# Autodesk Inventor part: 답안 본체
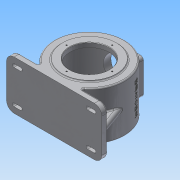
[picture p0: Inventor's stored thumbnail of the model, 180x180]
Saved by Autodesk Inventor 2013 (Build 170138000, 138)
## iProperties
Created: 2015-06
Part Number: 답안 본체
Material: 알루미늄 6061
Document SubType Name: Modeling
Designer: Administrator
Density: 2.71 g/cm^3
Mass: 3270.96 g
Surface Area: 2314.15 cm^2
Volume: 1207 cm^3
Author: Administrator
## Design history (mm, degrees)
sketch "스케치1"
  geometry: L1 (115, 14)-(115, 0); L2 (115, 0)-(-115, 0); L3 (-115, 0)-(-115, 14); L4 (-115, 14)-(-46.733, 14); L5 (46.733, 14)-(115, 14); A1 r 85 centre (0, 85) between (46.733, 14) and (-46.733, 14); 2 further points
  constraints: 10 end point, 3 parallel, 2 coincident, 2 horizontal, 2 perpendicular, 2 point on circle, 1 centre point, 1 collinear, 1 midpoint, 1 vertical alignment
  dimensions: "d1" = 85 distance of point (0, 0) A1.centre; "d2" = 230 distance between parallel lines of L1 L3; "d4" = 85 radius of A1; "d5" = 14 distance between parallel lines of L2 L5
extrude "돌출1" new body sketch "스케치1" distance "d6" = 118; taper "d7" = 0 deg
fillet "모깎기1" dims "d8" = 3
fillet "모깎기2" dims "d9" = 18
sketch "스케치2"
  geometry: L1 (-97, 0)-(97, 0) reference; C1 r 65 at (0, 85); A1 r 85 centre (0, 85) between (53.953, 19.318) and (-53.953, 19.318) reference; 2 further points
  constraints: 1 centre point, 1 coincident, 1 midpoint, 1 vertical alignment
  dimensions: "d10" = 130 diameter of C1
extrude "돌출2" join sketch "스케치2" distance "d11" = 3; taper "d12" = 0 deg
hole "구멍1" diameter "d15" = 95; stored, may be unused: countersink angle "d19" = 90 deg, drill point angle "d21" = 0 deg; dims "d13" = 10, "d14" = 10, "d16" = 6, "d17" = 4, "d18" = 2, "d20" = 11
sketch "스케치3"
  geometry: C1 r 77 at (0, 0); A1 r 85 centre (0, 0) between (53.953, -65.682) and (-53.953, -65.682) reference; 1 further point
  constraints: 1 centre point, 1 coincident
  dimensions: "d22" = 154 diameter of C1
extrude "돌출3" cut sketch "스케치3" distance "d23" = 102; taper "d24" = 0 deg
sketch "스케치4"
  geometry: C1 r 47.5 at (0, 0) reference; 2 further points
  constraints: 1 vertical alignment
  dimensions: "d25" = 55 distance of point (0, 55) C1.centre
hole "구멍2" sketch "스케치4" at (0, 55) diameter "d26" = 3.242; stored, may be unused: countersink angle "d30" = 90 deg, drill point angle "d32" = 0 deg; dims "d27" = 6, "d28" = 4, "d29" = 2, "d31" = 12
sketch "스케치5"
  geometry: C1 r 31 at (0, 0); A1 r 85 centre (0, 0) between (53.953, -65.682) and (-53.953, -65.682) reference; 1 further point
  constraints: 1 centre point, 1 coincident
  dimensions: "d36" = 62 diameter of C1
extrude "돌출4" join sketch "스케치5" distance "d37" = 3.5; taper "d38" = 0 deg
feature "면 기울기1" dims angle "d41" = 25 deg
sketch "스케치7"
  geometry: C1 r 65 at (0, 85); A1 r 85 centre (0, 85) between (53.953, 19.318) and (-53.953, 19.318) reference; 1 further point
  constraints: 1 centre point, 1 coincident
  dimensions: "d42" = 130 diameter of C1
extrude "돌출6" join sketch "스케치7" distance "d43" = 13; taper "d44" = 0 deg
hole "구멍3" diameter "d47" = 30; stored, may be unused: countersink angle "d51" = 90 deg, drill point angle "d53" = 0 deg; dims "d45" = 10, "d46" = 10, "d48" = 6, "d49" = 47, "d50" = 14, "d52" = 17
fillet "모깎기3" dims "d54" = 0.3
fillet "모깎기4" dims "d55" = 3
node "작업 평면2"
  node "작업 평면1"
sketch "스케치8"
  geometry: L1 (42.5, 16.5)-(-42.5, 16.5); L2 (-42.5, 16.5)-(-42.5, 101.5); L3 (-42.5, 101.5)-(42.5, 101.5); L4 (42.5, 101.5)-(42.5, 16.5); L5 (115, 18)-(115, 100) reference; 4 further points
  constraints: 8 end point, 3 midpoint, 2 parallel, 1 horizontal, 1 horizontal alignment, 1 perpendicular, 1 vertical alignment
  dimensions: "d57" = 85 distance of L1.start L1.end; "d59" = 85 distance of L1.end L2.end
extrude "돌출7" join sketch "스케치8" stored distance "d60" = 13; taper "d61" = 0 deg
sketch "스케치9"
  geometry: L1 (-42.5, -101.5)-(-42.5, -16.5) reference; L2 (-35.5, -23.5)-(35.5, -23.5); L3 (35.5, -23.5)-(35.5, -94.5); L4 (35.5, -94.5)-(-35.5, -94.5); L5 (-35.5, -94.5)-(-35.5, -23.5); 7 further points
  constraints: 8 end point, 3 coincident, 3 midpoint, 2 parallel, 1 horizontal, 1 horizontal alignment, 1 perpendicular, 1 vertical alignment
  dimensions: "d62" = 71 distance of L2.start L2.end; "d64" = 71 distance of L2.end L3.end
hole "구멍4" sketch "스케치9" at (-35.5, -23.5), (-35.5, -94.5), (35.5, -23.5), (35.5, -94.5) diameter "d65" = 3.242; stored, may be unused: countersink angle "d69" = 90 deg, drill point angle "d71" = 118 deg; dims "d66" = 10, "d67" = 47, "d68" = 14, "d70" = 13
sketch "스케치10"
  geometry: L1 (-42.5, -101.5)-(-42.5, -16.5) reference; 3 further points
  constraints: 1 horizontal alignment, 1 midpoint, 1 vertical alignment
hole "구멍5" sketch "스케치10" at (0, -59) diameter "d72" = 70; stored, may be unused: countersink angle "d76" = 90 deg, drill point angle "d78" = 0 deg; dims "d73" = 10, "d74" = 47, "d75" = 14, "d77" = 13
fillet "모깎기5" dims "d79" = 7
sketch "스케치11"
  geometry: L1 (25.143, 109)-(41.143, 109); L2 (41.143, 91)-(25.143, 91); L3 (25.143, 27)-(41.143, 27); L4 (41.143, 9)-(25.143, 9); A1 r 18 centre (41.143, 100) between (59.143, 100) and (41.143, 118) reference; A2 r 18 centre (41.143, 18) between (41.143, 0) and (59.143, 18) reference; A3 r 9 centre (41.143, 100) between (41.143, 91) and (41.143, 109); A4 r 9 centre (25.143, 100) between (25.143, 109) and (25.143, 91); A5 r 9 centre (41.143, 18) between (41.143, 9) and (41.143, 27); A6 r 9 centre (25.143, 18) between (25.143, 27) and (25.143, 9); 1 further point
  constraints: 8 end point, 8 point on circle, 8 tangent, 4 centre point, 3 parallel, 1 coincident, 1 concentric, 1 horizontal, 1 horizontal alignment
  dimensions: "d81" = 16 distance of A1.centre A4.centre; "d82" = 16 distance of A2.centre A6.centre; "d83" = 18 distance between parallel lines of L2 L1; "d84" = 18 distance between parallel lines of L4 L3
extrude "돌출8" join sketch "스케치11" distance "d85" = 3; taper "d86" = 0 deg
sketch "스케치12"
  geometry: L1 (41.143, 91)-(25.143, 91) reference; L2 (25.143, 109)-(41.143, 109) reference; L3 (41.143, 9)-(25.143, 9) reference; L4 (25.143, 27)-(41.143, 27) reference; L5 (41.143, 118)-(0, 118) reference; L6 (0, 0)-(0, 118) reference; L7 (41.143, 0)-(0, 0) reference; L8 (59.143, 100)-(59.143, 18) reference; L9 (41.143, 96)-(25.143, 96); L10 (25.143, 104)-(41.143, 104); L11 (41.143, 14)-(25.143, 14); L12 (25.143, 22)-(41.143, 22); A1 r 9 centre (41.143, 100) between (41.143, 91) and (41.143, 109) reference; A2 r 9 centre (25.143, 100) between (25.143, 109) and (25.143, 91) reference; A3 r 9 centre (41.143, 18) between (41.143, 9) and (41.143, 27) reference; A4 r 9 centre (25.143, 18) between (25.143, 27) and (25.143, 9) reference; A5 r 18 centre (41.143, 100) between (59.143, 100) and (41.143, 118) reference; A6 r 18 centre (41.143, 18) between (41.143, 0) and (59.143, 18) reference; A7 r 4 centre (41.143, 100) between (41.143, 96) and (41.143, 104); A8 r 4 centre (25.143, 100) between (25.143, 104) and (25.143, 96); A9 r 4 centre (41.143, 18) between (41.143, 14) and (41.143, 22); A10 r 4 centre (25.143, 18) between (25.143, 22) and (25.143, 14); 1 further point
  constraints: 8 end point, 8 point on circle, 4 centre point, 6 other
  dimensions: "d87" = 8 distance between parallel lines of L11 L12; "d89" = 8 distance between parallel lines of L9 L10
extrude "돌출9" cut sketch "스케치12" stored distance "d90" = 0; taper "d91" = 0 deg
node "작업 평면3"
sketch "스케치13"
  geometry: L1 (97, 14)-(115, 14) reference; L2 (115, 14)-(115, 0) reference; L3 (109, 14)-(84.87, 80.297); A1 r 85 centre (0, 85) between (53.953, 19.318) and (-53.953, 19.318) reference; 1 further point
  constraints: 2 end point, 1 point on circle, 1 point on line
  dimensions: "d92" = 110 deg angle of L3 L1; "d93" = 6 distance from line of L2 L3.start
feature "리브1" sketch "스케치13" dims "d94" = 1, "d95" = 15, "d96" = 0, "d97" = 0, "d98" = 1, "d99" = 1
fillet "모깎기6" dims "d100" = 7.5
chamfer "모따기1" distance "d101" = 1; stored, may be unused: second distance "d102" = 2, angle "d103" = 45 deg
fillet "모깎기7" dims "d104" = 3
node "작업 평면4"
sketch "스케치14"
  geometry: L1 (77.036, 120.923)-(0, 85); L2 (0, 85)-(85, 85); A1 r 85 centre (0, 85) between (53.953, 19.318) and (-53.953, 19.318) reference; 1 further point
  constraints: 4 end point, 2 point on circle, 1 horizontal
  dimensions: "d105" = 25 deg angle of L1 L2
node "작업 평면6"
  node "작업 평면5"
sketch "스케치15"
  geometry: L1 (-79.424, 59)-(82, 59) reference; L2 (65, 62)-(-65, 62) reference; 4 further points
  constraints: 1 midpoint, 1 vertical alignment, 1 other
  dimensions: "d107" = 59 distance from line of L1 point (0, 0)
feature "엠보싱1" sketch "스케치15" dims "d1" = 85, "d2" = 230, "d4" = 85, "d5" = 14, "d108" = 0.5, "d109" = 0
node "솔리드1"
pattern_circular "원형 패턴1" dims angle "d34" = 360 deg
mirror "대칭1"
mirror "대칭2"
node "투영된 루프2"
other parameters: "d3" = 14, "d56" = 3, "d106" = 5
